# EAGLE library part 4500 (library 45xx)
Industrial CONTROL UNIT
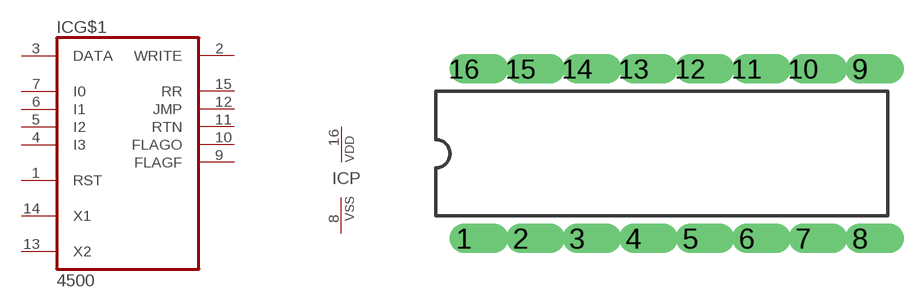
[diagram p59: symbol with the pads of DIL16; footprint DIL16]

Designator prefix IC; gates G$1=4500 P=PWRN

## 4500N  [DIL16]
1  G$1:RST  in
2  G$1:WRITE  out
3  G$1:DATA
4  G$1:I3  in
5  G$1:I2  in
6  G$1:I1  in
7  G$1:I0  in
8  P:VSS  pwr
9  G$1:FLAGF  out
10  G$1:FLAGO  out
11  G$1:RTN  out
12  G$1:JMP  out
13  G$1:X2  in
14  G$1:X1  out
15  G$1:RR  out
16  P:VDD  pwr

## Footprint DIL16 (pad centres in mm)
Dual In Line
drill 0.813 offset: 1 -8.89,-3.81; 2 -6.35,-3.81; 3 -3.81,-3.81; 4 -1.27,-3.81; 5 1.27,-3.81; 6 3.81,-3.81; 7 6.35,-3.81; 8 8.89,-3.81; 9 8.89,3.81; 10 6.35,3.81; 11 3.81,3.81; 12 1.27,3.81; 13 -1.27,3.81; 14 -3.81,3.81; 15 -6.35,3.81; 16 -8.89,3.81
